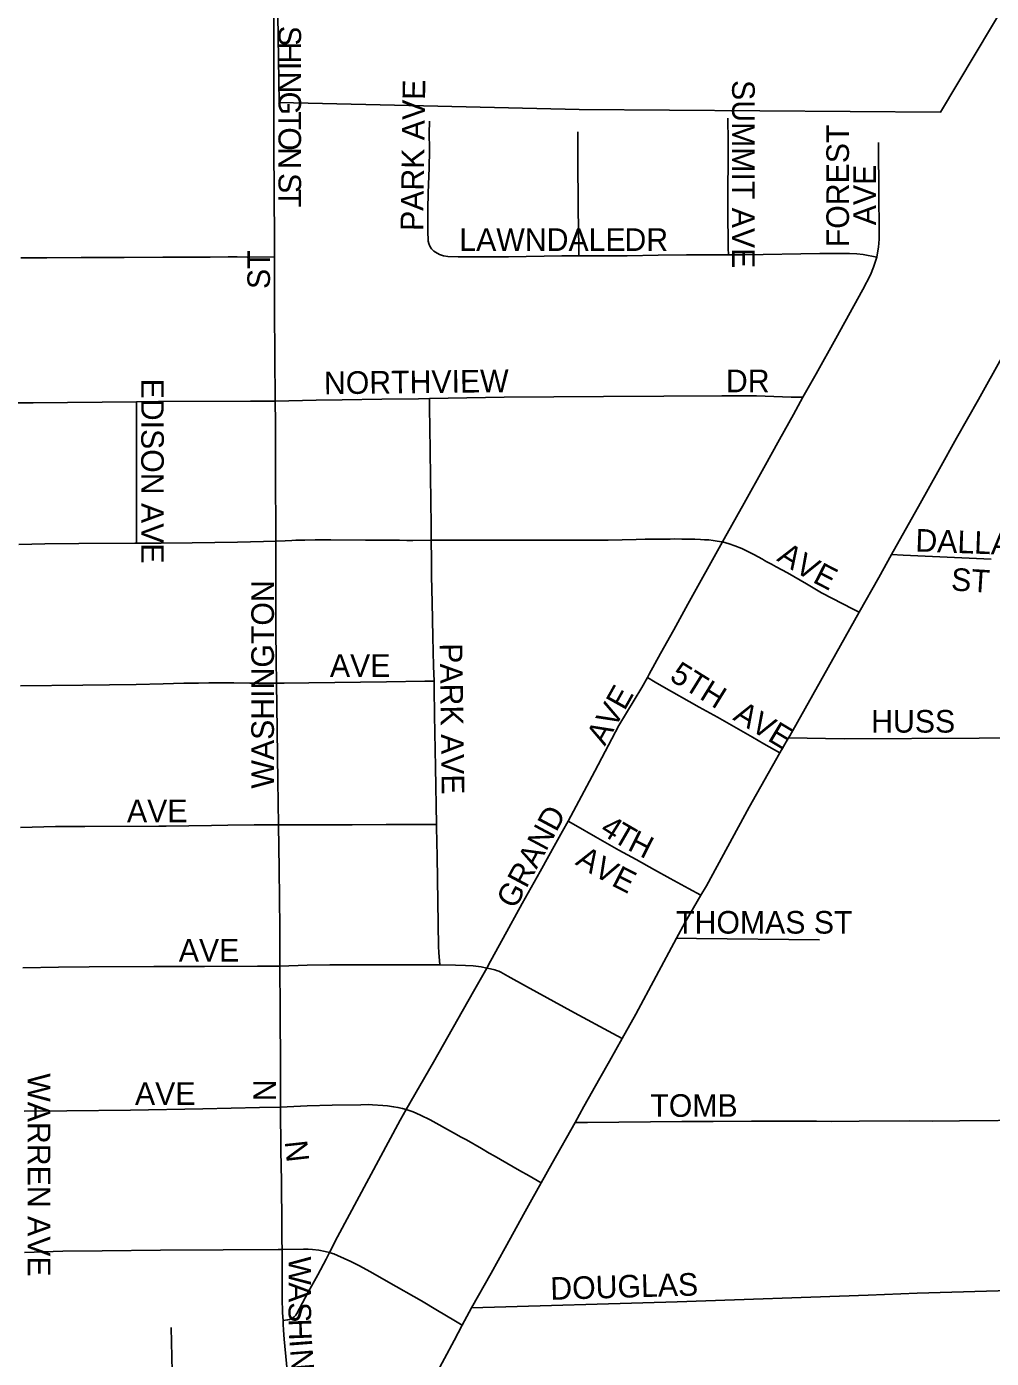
# Model space of a CAD drawing. Extents: x 1772825 to 1773716, y 1138558 to 1139032.
# Drawn here: x 1773348.22 to 1773356.3, y 1138891.46 to 1138902.61 of the extents above; entities that cross this region are included whole.
import ezdxf

# ---------------------------------------------------------------- set-up
doc = ezdxf.new("R2010")
doc.units = 0
for name, color, linetype in [('GM_X_City_Street', 7, 'Continuous'), ('GM_X_City_Street_Text', 7, 'Continuous'), ('GM_X_Corporation', 7, 'Continuous'), ('GM_X_State_Route', 7, 'Continuous')]:
    doc.layers.add(name, color=color, linetype=linetype)

msp = doc.modelspace()

# ---------------------------------------------------------------- linework, layer by layer
at = {"layer": 'GM_X_City_Street'}
for points in [[(1773350.292, 1138901.88), (1773350.293, 1138902.175), (1773350.293, 1138902.608), (1773350.289, 1138902.814), (1773350.286, 1138902.913), (1773350.285, 1138902.946), (1773350.282, 1138902.981), (1773350.28, 1138903.006), (1773350.275, 1138903.035), (1773350.269, 1138903.07), (1773350.259, 1138903.112), (1773350.238, 1138903.185), (1773350.224, 1138903.223), (1773350.198, 1138903.273), (1773350.17, 1138903.325), (1773350.047, 1138903.542), (1773349.996, 1138903.653), (1773349.984, 1138903.686), (1773349.979, 1138903.708), (1773349.975, 1138903.741)], [(1773350.299, 1138900.686), (1773350.298, 1138900.82), (1773350.298, 1138900.827), (1773350.292, 1138901.601), (1773350.292, 1138901.88)], [(1773354.1, 1138900.702), (1773354.099, 1138900.758), (1773354.096, 1138901.084), (1773354.097, 1138901.651), (1773354.094, 1138901.847)], [(1773351.622, 1138900.744), (1773351.613, 1138900.754), (1773351.599, 1138900.775), (1773351.591, 1138900.797), (1773351.586, 1138900.816), (1773351.581, 1138900.903), (1773351.583, 1138901.085), (1773351.584, 1138901.221), (1773351.593, 1138901.431), (1773351.596, 1138901.579), (1773351.594, 1138901.729), (1773351.595, 1138901.81), (1773351.597, 1138901.822)], [(1773352.847, 1138900.694), (1773352.846, 1138900.761), (1773352.841, 1138901.088), (1773352.841, 1138901.261), (1773352.84, 1138901.347), (1773352.84, 1138901.568), (1773352.839, 1138901.656), (1773352.838, 1138901.732)], [(1773355.342, 1138900.683), (1773355.35, 1138900.719), (1773355.357, 1138900.768), (1773355.362, 1138900.833), (1773355.362, 1138900.932), (1773355.36, 1138901.187), (1773355.358, 1138901.644)], [(1773351.622, 1138900.744), (1773351.627, 1138900.739), (1773351.633, 1138900.734), (1773351.647, 1138900.724), (1773351.679, 1138900.706), (1773351.714, 1138900.695), (1773351.75, 1138900.689), (1773351.837, 1138900.687), (1773352.259, 1138900.687), (1773352.706, 1138900.694), (1773352.847, 1138900.694)], [(1773354.1, 1138900.702), (1773354.233, 1138900.702), (1773354.866, 1138900.713), (1773355.114, 1138900.714), (1773355.175, 1138900.712), (1773355.229, 1138900.705), (1773355.342, 1138900.683)], [(1773348.174, 1138900.678), (1773348.391, 1138900.678), (1773348.677, 1138900.68), (1773349.038, 1138900.681), (1773349.361, 1138900.683), (1773349.499, 1138900.684), (1773349.611, 1138900.684), (1773349.76, 1138900.684), (1773349.91, 1138900.685), (1773349.985, 1138900.686), (1773350.07, 1138900.684), (1773350.299, 1138900.686)], [(1773350.303, 1138899.478), (1773350.298, 1138900.237), (1773350.299, 1138900.686)], [(1773352.847, 1138900.694), (1773353.103, 1138900.695), (1773353.252, 1138900.694), (1773353.513, 1138900.699), (1773353.748, 1138900.702), (1773354.059, 1138900.702), (1773354.1, 1138900.702)], [(1773354.724, 1138899.51), (1773354.835, 1138899.707), (1773354.999, 1138900.001), (1773355.225, 1138900.413), (1773355.289, 1138900.535), (1773355.315, 1138900.598), (1773355.342, 1138900.683)], [(1773350.303, 1138899.478), (1773350.648, 1138899.486), (1773350.865, 1138899.489), (1773351.198, 1138899.495), (1773351.503, 1138899.498), (1773351.595, 1138899.5)], [(1773351.595, 1138899.5), (1773352.221, 1138899.511), (1773353.054, 1138899.517), (1773353.559, 1138899.52), (1773354.045, 1138899.522), (1773354.187, 1138899.521), (1773354.336, 1138899.521), (1773354.626, 1138899.512), (1773354.724, 1138899.51)], [(1773351.609, 1138898.312), (1773351.61, 1138898.436), (1773351.599, 1138899.262), (1773351.597, 1138899.412), (1773351.595, 1138899.5)], [(1773354.05, 1138898.298), (1773354.065, 1138898.325), (1773354.231, 1138898.624), (1773354.397, 1138898.919), (1773354.529, 1138899.156), (1773354.644, 1138899.366), (1773354.724, 1138899.51)], [(1773348.151, 1138899.462), (1773348.275, 1138899.464), (1773349.142, 1138899.473)], [(1773349.142, 1138899.473), (1773349.327, 1138899.475), (1773350.098, 1138899.478), (1773350.303, 1138899.478)], [(1773349.142, 1138898.287), (1773349.142, 1138898.332), (1773349.142, 1138899.381), (1773349.142, 1138899.473)], [(1773350.308, 1138898.304), (1773350.308, 1138898.494), (1773350.307, 1138898.725), (1773350.307, 1138899.023), (1773350.306, 1138899.147), (1773350.306, 1138899.295), (1773350.303, 1138899.478)], [(1773348.157, 1138898.276), (1773348.375, 1138898.283), (1773348.658, 1138898.286), (1773349.128, 1138898.287), (1773349.142, 1138898.287)], [(1773349.142, 1138898.287), (1773349.349, 1138898.289), (1773349.607, 1138898.292), (1773349.797, 1138898.295), (1773349.988, 1138898.297), (1773350.205, 1138898.303), (1773350.308, 1138898.304)], [(1773350.308, 1138898.304), (1773350.386, 1138898.309), (1773350.443, 1138898.311), (1773350.477, 1138898.312), (1773350.552, 1138898.313), (1773350.639, 1138898.316), (1773350.771, 1138898.316), (1773351.061, 1138898.313), (1773351.185, 1138898.313), (1773351.235, 1138898.312), (1773351.296, 1138898.312), (1773351.346, 1138898.312), (1773351.407, 1138898.311), (1773351.457, 1138898.31), (1773351.609, 1138898.312)], [(1773350.315, 1138897.117), (1773350.313, 1138897.311), (1773350.31, 1138897.559), (1773350.309, 1138897.844), (1773350.31, 1138897.966), (1773350.309, 1138898.114), (1773350.308, 1138898.207), (1773350.308, 1138898.304)], [(1773351.609, 1138898.312), (1773351.746, 1138898.313), (1773352.246, 1138898.313), (1773352.502, 1138898.313), (1773352.863, 1138898.313), (1773353.093, 1138898.314), (1773353.328, 1138898.319), (1773353.403, 1138898.321), (1773353.55, 1138898.323), (1773353.612, 1138898.323), (1773353.649, 1138898.324), (1773353.71, 1138898.323), (1773353.771, 1138898.323), (1773353.819, 1138898.321), (1773353.866, 1138898.32), (1773353.9, 1138898.317), (1773353.935, 1138898.315), (1773353.971, 1138898.311), (1773354.007, 1138898.306), (1773354.044, 1138898.3), (1773354.05, 1138898.298)], [(1773351.634, 1138897.133), (1773351.63, 1138897.258), (1773351.625, 1138897.503), (1773351.619, 1138897.791), (1773351.614, 1138898.013), (1773351.612, 1138898.163), (1773351.609, 1138898.3), (1773351.609, 1138898.312)], [(1773353.422, 1138897.163), (1773353.437, 1138897.19), (1773353.531, 1138897.364), (1773353.643, 1138897.563), (1773353.761, 1138897.777), (1773354.05, 1138898.298)], [(1773354.05, 1138898.298), (1773354.106, 1138898.284), (1773354.154, 1138898.267), (1773354.212, 1138898.243), (1773354.279, 1138898.21), (1773354.312, 1138898.193), (1773354.385, 1138898.153), (1773354.403, 1138898.143), (1773354.421, 1138898.133), (1773354.461, 1138898.112), (1773354.501, 1138898.091), (1773354.594, 1138898.041), (1773354.753, 1138897.947), (1773354.881, 1138897.873), (1773355.146, 1138897.736), (1773355.196, 1138897.71)], [(1773355.467, 1138898.193), (1773355.565, 1138898.188), (1773356.3, 1138898.155)], [(1773352.757, 1138895.96), (1773352.98, 1138896.379), (1773353.181, 1138896.761), (1773353.375, 1138897.08), (1773353.422, 1138897.163)], [(1773353.422, 1138897.163), (1773353.486, 1138897.125), (1773353.54, 1138897.093), (1773353.856, 1138896.916), (1773354.008, 1138896.83), (1773354.302, 1138896.663), (1773354.398, 1138896.609), (1773354.532, 1138896.532)], [(1773348.171, 1138897.094), (1773348.693, 1138897.1), (1773349.139, 1138897.105), (1773349.365, 1138897.11), (1773349.538, 1138897.115), (1773349.662, 1138897.117), (1773349.748, 1138897.118), (1773349.822, 1138897.118), (1773349.884, 1138897.118), (1773349.957, 1138897.118), (1773350.09, 1138897.117), (1773350.315, 1138897.117)], [(1773350.315, 1138897.117), (1773350.379, 1138897.117), (1773350.586, 1138897.118), (1773351.236, 1138897.128), (1773351.557, 1138897.132), (1773351.634, 1138897.133)], [(1773350.332, 1138895.931), (1773350.327, 1138896.298), (1773350.324, 1138896.502), (1773350.32, 1138896.728), (1773350.315, 1138897.117)], [(1773351.655, 1138895.933), (1773351.645, 1138896.414), (1773351.639, 1138896.849), (1773351.635, 1138897.071), (1773351.634, 1138897.133)], [(1773357.974, 1138896.668), (1773357.294, 1138896.659), (1773356.2, 1138896.655), (1773355.07, 1138896.65), (1773354.603, 1138896.658)], [(1773348.171, 1138895.907), (1773348.462, 1138895.915), (1773348.71, 1138895.917), (1773349.329, 1138895.919), (1773349.39, 1138895.92), (1773349.771, 1138895.924), (1773349.907, 1138895.927), (1773350.128, 1138895.929), (1773350.274, 1138895.931), (1773350.332, 1138895.931)], [(1773350.332, 1138895.931), (1773350.592, 1138895.93), (1773350.949, 1138895.931), (1773351.233, 1138895.934), (1773351.556, 1138895.934), (1773351.655, 1138895.933)], [(1773350.342, 1138894.746), (1773350.342, 1138895.067), (1773350.338, 1138895.559), (1773350.332, 1138895.931)], [(1773351.682, 1138894.758), (1773351.675, 1138894.862), (1773351.672, 1138894.911), (1773351.659, 1138895.664), (1773351.655, 1138895.909), (1773351.655, 1138895.933)], [(1773352.075, 1138894.731), (1773352.107, 1138894.788), (1773352.212, 1138894.981), (1773352.373, 1138895.272), (1773352.523, 1138895.54), (1773352.655, 1138895.777), (1773352.71, 1138895.876), (1773352.757, 1138895.96)], [(1773352.757, 1138895.96), (1773352.823, 1138895.924), (1773352.987, 1138895.83), (1773353.182, 1138895.719), (1773353.326, 1138895.639), (1773353.481, 1138895.553), (1773353.613, 1138895.48), (1773353.766, 1138895.397), (1773353.869, 1138895.34)], [(1773353.665, 1138894.981), (1773353.833, 1138894.979), (1773354.864, 1138894.968)], [(1773348.189, 1138894.733), (1773348.489, 1138894.738), (1773348.746, 1138894.74), (1773349.288, 1138894.744), (1773349.71, 1138894.744), (1773350.154, 1138894.746), (1773350.342, 1138894.746)], [(1773350.342, 1138894.746), (1773350.571, 1138894.754), (1773350.76, 1138894.758), (1773350.995, 1138894.759), (1773351.36, 1138894.757), (1773351.49, 1138894.757), (1773351.618, 1138894.758), (1773351.682, 1138894.758)], [(1773350.349, 1138893.565), (1773350.348, 1138893.889), (1773350.344, 1138894.383), (1773350.342, 1138894.746)], [(1773351.401, 1138893.546), (1773351.63, 1138893.944), (1773351.833, 1138894.303), (1773351.964, 1138894.535), (1773352.075, 1138894.731)], [(1773351.682, 1138894.758), (1773351.813, 1138894.756), (1773351.898, 1138894.752), (1773351.961, 1138894.748), (1773352.03, 1138894.74), (1773352.075, 1138894.731)], [(1773352.075, 1138894.731), (1773352.107, 1138894.725), (1773352.144, 1138894.716), (1773352.158, 1138894.711), (1773352.177, 1138894.704), (1773352.194, 1138894.696), (1773352.253, 1138894.664), (1773352.409, 1138894.576), (1773352.812, 1138894.355), (1773353.131, 1138894.184), (1773353.21, 1138894.142)], [(1773350.349, 1138893.565), (1773350.572, 1138893.576), (1773350.781, 1138893.583), (1773351.021, 1138893.586), (1773351.088, 1138893.587), (1773351.119, 1138893.586), (1773351.204, 1138893.58), (1773351.243, 1138893.577), (1773351.295, 1138893.57), (1773351.331, 1138893.564), (1773351.369, 1138893.555), (1773351.4, 1138893.546), (1773351.401, 1138893.546)], [(1773348.2, 1138893.533), (1773348.558, 1138893.535), (1773349.092, 1138893.542), (1773349.697, 1138893.551), (1773350.172, 1138893.563), (1773350.349, 1138893.565)], [(1773350.361, 1138892.373), (1773350.36, 1138892.454), (1773350.36, 1138892.568), (1773350.355, 1138892.95), (1773350.352, 1138893.2), (1773350.349, 1138893.565)], [(1773350.759, 1138892.348), (1773350.826, 1138892.479), (1773351.35, 1138893.456), (1773351.401, 1138893.546)], [(1773351.401, 1138893.546), (1773351.458, 1138893.526), (1773351.521, 1138893.499), (1773351.601, 1138893.46), (1773351.796, 1138893.351), (1773351.861, 1138893.315), (1773351.905, 1138893.292), (1773352.033, 1138893.219), (1773352.096, 1138893.182), (1773352.138, 1138893.158), (1773352.192, 1138893.127), (1773352.245, 1138893.097), (1773352.298, 1138893.066), (1773352.349, 1138893.036), (1773352.43, 1138892.991), (1773352.532, 1138892.933)], [(1773352.815, 1138893.437), (1773352.92, 1138893.438), (1773353.711, 1138893.446), (1773353.971, 1138893.446), (1773354.294, 1138893.448), (1773354.467, 1138893.448), (1773354.715, 1138893.449), (1773354.839, 1138893.448), (1773354.962, 1138893.447), (1773355.194, 1138893.45), (1773355.615, 1138893.451), (1773355.813, 1138893.449), (1773356.035, 1138893.451), (1773356.686, 1138893.458), (1773356.91, 1138893.459), (1773357.207, 1138893.464), (1773357.405, 1138893.464), (1773357.552, 1138893.464), (1773357.989, 1138893.467)], [(1773348.203, 1138892.349), (1773348.525, 1138892.359), (1773348.853, 1138892.363), (1773349.342, 1138892.369), (1773349.869, 1138892.37), (1773350.329, 1138892.373), (1773350.361, 1138892.373)], [(1773350.361, 1138892.373), (1773350.541, 1138892.376), (1773350.581, 1138892.376), (1773350.617, 1138892.373), (1773350.668, 1138892.368), (1773350.722, 1138892.358), (1773350.759, 1138892.348)], [(1773350.369, 1138891.781), (1773350.365, 1138891.845), (1773350.361, 1138891.968), (1773350.361, 1138892.092), (1773350.361, 1138892.373)], [(1773350.369, 1138891.781), (1773350.407, 1138891.784), (1773350.423, 1138891.788), (1773350.436, 1138891.793), (1773350.451, 1138891.802), (1773350.463, 1138891.811), (1773350.476, 1138891.825), (1773350.486, 1138891.839), (1773350.581, 1138892.018), (1773350.662, 1138892.162), (1773350.731, 1138892.292), (1773350.759, 1138892.348)], [(1773350.759, 1138892.348), (1773350.764, 1138892.347), (1773350.796, 1138892.338), (1773350.826, 1138892.325), (1773350.938, 1138892.273), (1773351.005, 1138892.24), (1773351.103, 1138892.187), (1773351.253, 1138892.101), (1773351.53, 1138891.943), (1773351.664, 1138891.864), (1773351.8, 1138891.782), (1773351.871, 1138891.74)], [(1773351.947, 1138891.885), (1773353.671, 1138891.937), (1773355.271, 1138891.993), (1773355.68, 1138892.008), (1773356.553, 1138892.035), (1773356.56, 1138892.035)], [(1773349.47, 1138889.785), (1773349.472, 1138889.851), (1773349.472, 1138889.897), (1773349.47, 1138890.109), (1773349.468, 1138890.232), (1773349.459, 1138890.537), (1773349.445, 1138891.107), (1773349.431, 1138891.72)], [(1773350.577, 1138889.815), (1773350.566, 1138889.921), (1773350.539, 1138890.199), (1773350.52, 1138890.384), (1773350.496, 1138890.588), (1773350.432, 1138891.071), (1773350.379, 1138891.622), (1773350.374, 1138891.699), (1773350.37, 1138891.748), (1773350.369, 1138891.781)]]:
    msp.add_lwpolyline(points, dxfattribs=at)
at = {"layer": 'GM_X_Corporation'}
msp.add_lwpolyline([(1773345.582, 1138917.161), (1773345.459, 1138910.409), (1773342.061, 1138910.472), (1773341.884, 1138907.12), (1773343.978, 1138907.136), (1773346.304, 1138907.152), (1773346.258, 1138903.753), (1773349.975, 1138903.741), (1773350.318, 1138903.719), (1773350.321, 1138903.081), (1773350.338, 1138901.979), (1773351.665, 1138901.948), (1773352.849, 1138901.918), (1773355.878, 1138901.897), (1773356.594, 1138903.099)], dxfattribs=at)
at = {"layer": 'GM_X_State_Route'}
for points in [[(1773352.454, 1138892.793), (1773352.532, 1138892.933), (1773352.625, 1138893.098), (1773352.815, 1138893.437), (1773352.89, 1138893.571), (1773353.023, 1138893.809), (1773353.103, 1138893.952), (1773353.21, 1138894.142), (1773353.324, 1138894.345), (1773353.665, 1138894.981), (1773353.735, 1138895.11), (1773353.869, 1138895.34), (1773353.916, 1138895.419), (1773354.274, 1138896.078), (1773354.532, 1138896.532), (1773354.603, 1138896.658), (1773354.614, 1138896.676), (1773355, 1138897.363), (1773355.196, 1138897.71), (1773355.196, 1138897.711), (1773355.36, 1138898.001), (1773355.467, 1138898.193), (1773355.506, 1138898.263), (1773355.692, 1138898.595), (1773355.868, 1138898.911), (1773356.012, 1138899.168), (1773356.196, 1138899.492), (1773356.401, 1138899.862)], [(1773351.559, 1138891.159), (1773351.804, 1138891.611), (1773351.871, 1138891.74), (1773351.947, 1138891.885), (1773352.112, 1138892.176), (1773352.229, 1138892.388), (1773352.397, 1138892.692), (1773352.454, 1138892.793)]]:
    msp.add_lwpolyline(points, dxfattribs=at)

# ---------------------------------------------------------------- texts
at = {"layer": 'GM_X_City_Street_Text'}
for s, height, rotation, p in [('S', 0.189, 270, (1773350.331, 1138902.62)), ('H', 0.189, 269.9928, (1773350.331, 1138902.487)), ('I', 0.189, 270, (1773350.331, 1138902.32)), ('N', 0.189, 269.9928, (1773350.331, 1138902.237)), ('G', 0.189, 269.9928, (1773350.331, 1138902.07)), ('PARK AVE', 0.1894, 89.1689, (1773351.543, 1138900.901)), ('SUMMIT AVE', 0.1894, 270, (1773354.131, 1138902.166)), ('T', 0.189, 269.9956, (1773350.331, 1138901.903)), ('O', 0.189, 269.9928, (1773350.331, 1138901.77)), ('FOREST', 0.1894, 90, (1773355.11, 1138900.766)), ('N', 0.189, 269.9928, (1773350.331, 1138901.603)), ('AVE', 0.1894, 90, (1773355.336, 1138900.95)), ('S', 0.189, 269.9956, (1773350.331, 1138901.387)), ('T', 0.189, 269.9956, (1773350.331, 1138901.253)), ('LAWNDALE', 0.1894, 0, (1773351.846, 1138900.735)), ('DR', 0.1894, 0, (1773353.229, 1138900.735)), ('ST', 0.1894, 90, (1773350.26, 1138900.416)), ('NORTHVIEW', 0.1894, 0.6724, (1773350.713, 1138899.535)), ('DR', 0.1894, 0, (1773354.079, 1138899.552)), ('EDISON AVE', 0.1894, 270, (1773349.181, 1138899.666)), ('DALLAS', 0.1894, 357.8801, (1773355.664, 1138898.219)), ('A', 0.189, 328.0803, (1773354.498, 1138898.146)), ('V', 0.189, 329.3658, (1773354.644, 1138898.056)), ('E', 0.189, 332.8524, (1773354.798, 1138897.965)), ('ST', 0.1894, 356.4254, (1773355.961, 1138897.893)), ('WASHINGTON', 0.1894, 90, (1773350.293, 1138896.233)), ('PARK AVE', 0.1894, 270.8286, (1773351.681, 1138897.449)), ('AVE', 0.1894, 0, (1773350.762, 1138897.169)), ('5TH', 0.1894, 328.2394, (1773353.598, 1138897.146)), ('AVE', 0.1894, 60.7528, (1773353.065, 1138896.584)), ('AVE', 0.1894, 329.0401, (1773354.13, 1138896.814)), ('HUSS', 0.1894, 0, (1773355.296, 1138896.702)), ('AVE', 0.1894, 0, (1773349.062, 1138895.952)), ('GRAND', 0.1894, 61.9202, (1773352.314, 1138895.217)), ('4', 0.189, 327.7132, (1773353.015, 1138895.863)), ('T', 0.189, 329.8039, (1773353.12, 1138895.797)), ('H', 0.189, 333.0571, (1773353.246, 1138895.724)), ('A', 0.189, 328.6202, (1773352.81, 1138895.602)), ('V', 0.189, 330.7612, (1773352.959, 1138895.512)), ('E', 0.189, 333.0328, (1773353.112, 1138895.426)), ('THOMAS ST', 0.1894, 0, (1773353.662, 1138895.019)), ('AVE', 0.1894, 0, (1773349.496, 1138894.785)), ('WARREN AVE', 0.1894, 270, (1773348.231, 1138893.85)), ('AVE', 0.1894, 0, (1773349.129, 1138893.585)), ('N', 0.189, 90, (1773350.31, 1138893.616)), ('TOMB', 0.1894, 0, (1773353.446, 1138893.485)), ('N', 0.189, 276.235, (1773350.382, 1138893.278)), ('W', 0.189, 270.0336, (1773350.415, 1138892.316)), ('DOUGLAS', 0.1894, 1.7348, (1773352.611, 1138891.952)), ('A', 0.189, 270.0379, (1773350.415, 1138892.1)), ('S', 0.189, 270.0455, (1773350.415, 1138891.933)), ('H', 0.189, 272.0108, (1773350.415, 1138891.792)), ('I', 0.189, 274.3992, (1773350.422, 1138891.617)), ('N', 0.189, 274.5306, (1773350.428, 1138891.534))]:
    msp.add_text(s, height=height, rotation=rotation, dxfattribs=at).set_placement(p)

doc.saveas('drawing.dxf')
